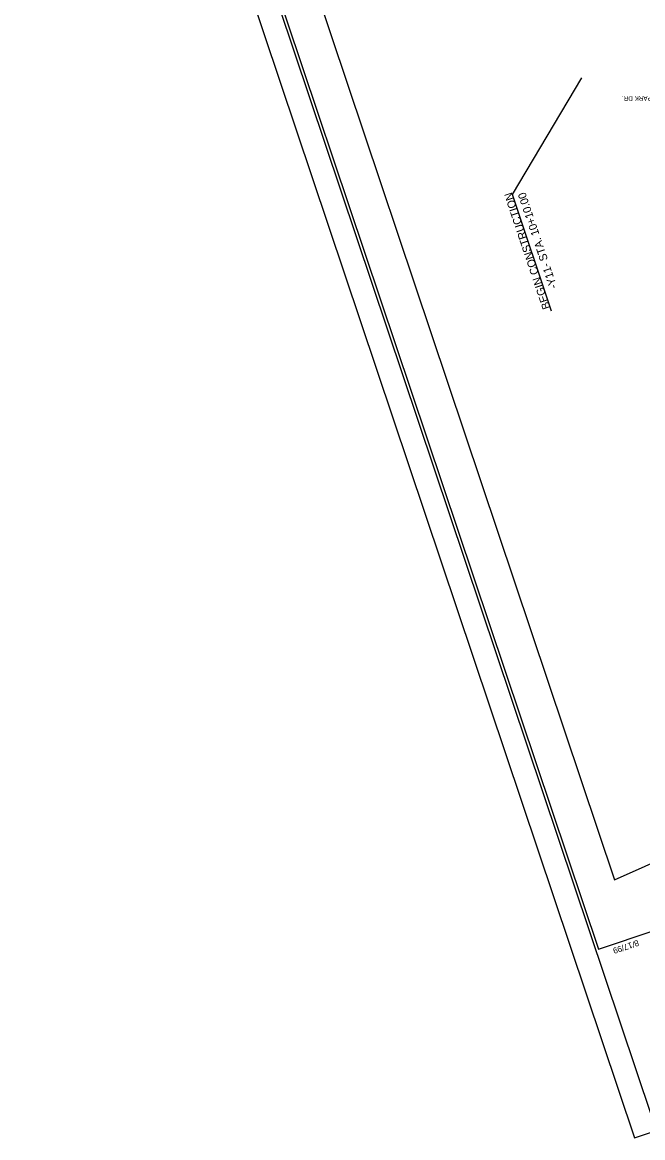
# Model space of a CAD drawing. Extents: x 1615436 to 1617010, y 903110 to 905055.
# Drawn here: x 1615436 to 1615979, y 903110 to 904086 of the extents above; entities that cross this region are included whole.
import ezdxf

# ---------------------------------------------------------------- set-up
doc = ezdxf.new("R2010")
doc.units = 0
for name, color, linetype in [('Exist DTM Regular Point Cogo Number', 7, 'Continuous'), ('Exist Structure Minor Pipes RCP 15 Inch Cogo Number', 7, 'Continuous'), ('Exist Structure Minor Pipes RCP 18 Inch Cogo Point CELL', 7, 'Continuous'), ('Exist Utilities Sanitary Sewer Manhole CELL', 7, 'Continuous'), ('Sheet Layout Plan Border', 7, 'Continuous'), ('Sheet Plan Layout CELL', 7, 'Continuous'), ('Sheet Sticker Exception Certification CELL', 7, 'Continuous')]:
    doc.layers.add(name, color=color, linetype=linetype)

msp = doc.modelspace()

# ---------------------------------------------------------------- linework, layer by layer
at = {"layer": 'Exist DTM Regular Point Cogo Number'}
msp.add_lwpolyline([(1616672.58, 903656.2), (1616919.77, 903656.8), (1616590.65, 904611.24), (1616386.84, 904624.44), (1616334.81, 904821.64), (1616466, 905009.57), (1615641.09, 904732.87), (1615700.02, 904557.19), (1615560.35, 904510.33), (1615954.19, 903336.21)], close=True, dxfattribs=at)
at = {"layer": 'Exist Structure Minor Pipes RCP 15 Inch Cogo Number'}
msp.add_line((1615940.18, 903275.48), (1615940.18, 903275.48), dxfattribs=at)
msp.add_lwpolyline([(1615463.14, 904697.64), (1615940.18, 903275.48), (1616935.67, 903609.4), (1616458.64, 905031.54)], close=True, dxfattribs=at)
at = {"layer": 'Exist Structure Minor Pipes RCP 18 Inch Cogo Point CELL'}
msp.add_line((1615865.08, 903935.68), (1615925.69, 904037.76), dxfattribs=at)
at = {"layer": 'Sheet Layout Plan Border'}
msp.add_lwpolyline([(1616986.86, 903464.68), (1616457.04, 905044.17), (1615456.82, 904708.68), (1615986.63, 903129.17)], close=True, dxfattribs=at)
at = {"layer": 'Sheet Plan Layout CELL'}
msp.add_line((1615899.32, 903833.59), (1615865.08, 903935.68), dxfattribs=at)
at = {"layer": 'Sheet Sticker Exception Certification CELL'}
msp.add_lwpolyline([(1617009.96, 903458.71), (1616474.57, 905054.81), (1615436.42, 904706.58), (1615971.81, 903110.48)], close=True, dxfattribs=at)

# ---------------------------------------------------------------- texts
at = {"layer": 'Exist Structure Minor Pipes RCP 15 Inch Cogo Number'}
msp.add_text('8/17/99', height=5.25, rotation=198.54318, dxfattribs=at).set_placement((1615974.6, 903283.62))
at = {"layer": 'Exist Utilities Sanitary Sewer Manhole CELL'}
msp.add_text('NORTHRIDGE PARK DR.', height=4, rotation=180.73519, dxfattribs=at).set_placement((1616025.53, 904022.29))
at = {"layer": 'Sheet Plan Layout CELL'}
for s, p in [('BEGIN CONSTRUCTION', (1615898.35, 903836.5)), ('-Y11- STA. 10+10.00 ', (1615904.29, 903854.55))]:
    msp.add_text(s, height=7, rotation=108.54317, dxfattribs=at).set_placement(p)

doc.saveas('drawing.dxf')
